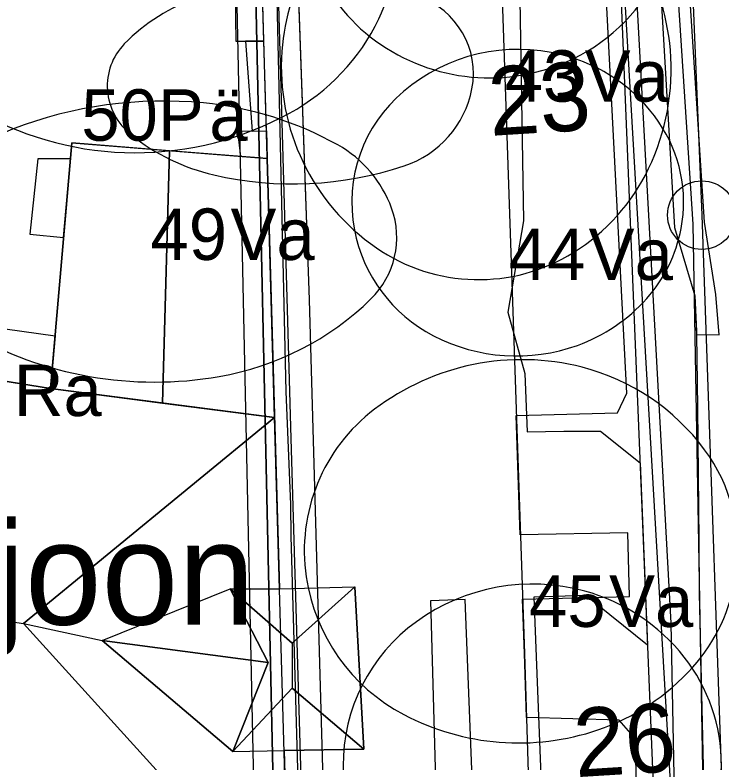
# Model space of a CAD drawing. Extents: x 738423 to 738903, y 6589762 to 6590172.
# Drawn here: x 738753.01 to 738773.59, y 6589853.54 to 6589875.33 of the extents above; entities that cross this region are included whole.
import ezdxf

# ---------------------------------------------------------------- set-up
doc = ezdxf.new("R2010")
doc.units = 0
for name, color, linetype in [('_1927_hoonestus', 7, 'Continuous'), ('_1927_katuse_kalded', 7, 'Continuous'), ('_1927_koordin_punktid_nr', 7, 'Continuous'), ('_1927_krundi_piir', 7, 'Continuous'), ('_a_olol_maapind', 7, 'Continuous'), ('_ajalooline_aadress', 7, 'Continuous'), ('a_dendro_II_Vkl_puu', 7, 'Continuous'), ('a_dendro_III_vk_puu', 7, 'Continuous'), ('a_dendro_puu_nr', 7, 'Continuous'), ('a_dendro_V_vk_puu', 7, 'Continuous'), ('a_kaitsealune_park', 7, 'Continuous'), ('a_LK_III_kodukakk', 7, 'Continuous'), ('Default', 7, 'Continuous'), ('plan_ala', 7, 'Continuous'), ('v_dp_jalak_liikumine', 7, 'Continuous'), ('v_olol_kitsendus_tehnov', 7, 'Continuous'), ('v_olol_kivimuur', 7, 'Continuous'), ('v_olol_transp_jjt_jalg', 7, 'Continuous'), ('v_olol_transp_tee', 7, 'Continuous')]:
    doc.layers.add(name, color=color, linetype=linetype)

# ---------------------------------------------------------------- blocks, each defined once
blk = doc.blocks.new('_U493')
at = {"layer": 'Default'}
for centre, radius, start, end in [((-0.002779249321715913, 0.004118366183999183), 0.010010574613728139, 80.44978915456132, 146.25517279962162), ((-0.0028357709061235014, 0.003782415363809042), 0.010351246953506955, 32.07722645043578, 80.44978915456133), ((-0.0017373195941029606, 0.003422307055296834), 0.011263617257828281, 146.2551727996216, 207.86384233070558), ((-0.003686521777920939, 0.0032492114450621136), 0.011355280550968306, 346.0222805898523, 32.077226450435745), ((-0.003267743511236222, 0.003144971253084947), 0.010923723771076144, 317.781064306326, 346.0222805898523), ((-0.0022155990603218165, 0.0031694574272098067), 0.010722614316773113, 207.8638423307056, 247.1920387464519), ((-0.002627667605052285, 0.0025642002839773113), 0.010059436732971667, 288.3253318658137, 317.78106430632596), ((-0.00255825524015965, 0.002354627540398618), 0.009838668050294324, 247.19203874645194, 288.3253318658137)]:
    blk.add_arc(centre, radius, start, end, dxfattribs=at)
blk = doc.blocks.new('_U494')
at = {"layer": 'Default'}
for centre, radius, start, end in [((-0.0012102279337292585, 0.0031557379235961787), 0.012828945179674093, 90.26069818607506, 149.67736093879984), ((-0.001211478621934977, 0.0034306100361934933), 0.012554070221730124, 36.73116784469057, 90.26069818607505), ((0.000498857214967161, 0.004706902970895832), 0.010420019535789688, 337.48443189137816, 36.73116784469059), ((-0.0032425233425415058, 0.004344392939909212), 0.010474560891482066, 149.67736093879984, 216.20034037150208), ((-0.0005155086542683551, 0.005127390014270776), 0.011518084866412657, 307.20500292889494, 337.48443189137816), ((-0.002245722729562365, 0.005073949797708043), 0.011709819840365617, 216.20034037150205, 248.7506077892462), ((-0.0015898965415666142, 0.006542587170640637), 0.013294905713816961, 279.06638207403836, 307.20500292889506), ((-0.0016145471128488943, 0.006697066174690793), 0.013451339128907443, 248.75060778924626, 279.06638207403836)]:
    blk.add_arc(centre, radius, start, end, dxfattribs=at)
blk = doc.blocks.new('_U495')
at = {"layer": 'Default'}
for centre, radius, start, end in [((0.001247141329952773, 0.003809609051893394), 0.008480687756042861, 44.522724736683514, 105.14224422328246), ((0.0013373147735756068, 0.003476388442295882), 0.008825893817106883, 105.14224422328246, 156.90409293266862), ((-0.00011059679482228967, 0.0024743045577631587), 0.01038502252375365, 350.25622703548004, 44.52272473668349), ((0.0028799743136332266, 0.0028185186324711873), 0.01050297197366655, 156.9040929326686, 204.0776996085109), ((0.0005376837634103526, 0.0023629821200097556), 0.009727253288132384, 308.7697621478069, 350.25622703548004), ((0.002304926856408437, 0.0025615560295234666), 0.009873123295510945, 204.0776996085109, 232.70014380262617), ((0.00146564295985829, 0.0012075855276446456), 0.008245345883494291, 263.520272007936, 308.7697621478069), ((0.0014993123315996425, 0.0015040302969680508), 0.008543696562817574, 232.70014380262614, 263.520272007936)]:
    blk.add_arc(centre, radius, start, end, dxfattribs=at)
blk = doc.blocks.new('_U496')
at = {"layer": 'Default'}
for centre, radius, start, end in [((0.001006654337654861, 0.005865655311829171), 0.010371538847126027, 41.52685359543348, 102.67231492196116), ((0.0011174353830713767, 0.005372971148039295), 0.010876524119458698, 102.67231492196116, 156.5695222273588), ((-0.0018463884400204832, 0.0033391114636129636), 0.014182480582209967, 349.9614071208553, 41.52685359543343), ((0.0043186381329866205, 0.003985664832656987), 0.014365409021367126, 156.56952222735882, 203.0187686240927), ((-0.0005003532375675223, 0.003100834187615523), 0.012815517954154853, 310.73435045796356, 349.96140712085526), ((0.003089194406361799, 0.0034633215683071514), 0.013029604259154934, 203.0187686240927, 232.53618152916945), ((0.0014401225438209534, 0.0013113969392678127), 0.01031847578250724, 232.5361815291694, 265.8052878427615), ((0.0014087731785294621, 0.0008839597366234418), 0.009889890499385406, 265.8052878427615, 310.7343504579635)]:
    blk.add_arc(centre, radius, start, end, dxfattribs=at)
blk = doc.blocks.new('_U497')
at = {"layer": 'Default'}
for centre, radius, start, end in [((-0.0002784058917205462, 0.0036950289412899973), 0.010329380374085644, 94.66436035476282, 151.30931070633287), ((-0.00027800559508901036, 0.0036901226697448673), 0.010334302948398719, 40.2654876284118, 94.66436035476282), ((-0.0011843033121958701, 0.0029224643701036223), 0.011522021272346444, 348.96331862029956, 40.265487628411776), ((0.0007686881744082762, 0.00312198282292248), 0.01152302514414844, 151.30931070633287, 204.69265836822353), ((-0.0007788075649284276, 0.0028433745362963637), 0.01110888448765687, 312.4366755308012, 348.96331862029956), ((0.0003699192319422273, 0.0029386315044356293), 0.011084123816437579, 204.69265836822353, 238.61349672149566), ((-0.00011649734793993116, 0.002118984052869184), 0.01012735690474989, 274.1151503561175, 312.43667553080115), ((-0.00011793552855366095, 0.0021389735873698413), 0.010147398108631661, 238.6134967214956, 274.1151503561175)]:
    blk.add_arc(centre, radius, start, end, dxfattribs=at)
blk = doc.blocks.new('_U500')
at = {"layer": 'Default'}
for centre, radius, start, end in [((-0.003181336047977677, 0.010726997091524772), 0.005594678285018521, 70.00824536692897, 154.4975713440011), ((-0.004341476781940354, 0.007538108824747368), 0.008988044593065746, 25.436486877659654, 70.00824536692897), ((0.011580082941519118, 0.0036853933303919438), 0.021949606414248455, 154.49757134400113, 194.18050981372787), ((-0.018263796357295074, 0.0009164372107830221), 0.024404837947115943, 358.8256663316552, 25.436486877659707), ((-0.0137456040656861, 0.0008238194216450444), 0.019885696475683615, 335.045242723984, 358.8256663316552), ((0.0065598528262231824, 0.0024168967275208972), 0.01677159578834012, 194.18050981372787, 228.62130685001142), ((-0.0020266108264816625, -0.004629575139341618), 0.006959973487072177, 294.2825804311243, 335.045242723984), ((-0.0012209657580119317, -0.006415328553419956), 0.005000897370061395, 228.6213068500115, 294.2825804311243)]:
    blk.add_arc(centre, radius, start, end, dxfattribs=at)
blk = doc.blocks.new('_U501')
at = {"layer": 'Default'}
for centre, radius, start, end in [((6.853040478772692e-05, 0.0017748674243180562), 0.0034801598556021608, 50.02426182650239, 98.69184032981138), ((0.00010234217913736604, 0.0015536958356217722), 0.003703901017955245, 98.69184032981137, 145.7521009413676), ((-0.0047346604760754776, -0.003954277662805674), 0.010956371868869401, 23.167488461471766, 50.0242618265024), ((0.007022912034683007, -0.003157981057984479), 0.012076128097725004, 145.7521009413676, 171.29949798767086), ((-0.01307393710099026, -0.007522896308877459), 0.020027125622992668, 345.8050064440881, 23.167488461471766), ((0.015367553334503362, -0.004434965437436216), 0.020517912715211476, 171.29949798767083, 202.7206439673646), ((0.0019149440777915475, -0.01006800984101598), 0.00593354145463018, 202.7206439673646, 263.18793889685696), ((0.0017704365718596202, -0.011277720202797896), 0.004715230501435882, 263.18793889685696, 345.8050064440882)]:
    blk.add_arc(centre, radius, start, end, dxfattribs=at)
blk = doc.blocks.new('_U502')
at = {"layer": 'Default'}
for centre, radius, start, end in [((0.0036572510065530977, 0.004633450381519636), 0.00959048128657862, 55.41358266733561, 119.34866517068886), ((0.004842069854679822, 0.0025263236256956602), 0.012007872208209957, 119.34866517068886, 155.37187783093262), ((-0.0003045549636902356, -0.0011124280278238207), 0.016569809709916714, 7.908336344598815, 55.413582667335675), ((0.010745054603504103, -0.00017977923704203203), 0.018501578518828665, 155.37187783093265, 184.22093899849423), ((-0.0007628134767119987, -0.0011760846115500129), 0.017032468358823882, 317.51230780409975, 7.908336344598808), ((0.010991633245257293, -0.00016158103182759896), 0.018748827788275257, 184.2209389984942, 213.03615061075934), ((0.005634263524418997, -0.0036455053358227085), 0.01235827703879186, 213.03615061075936, 248.72963133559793), ((0.004661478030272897, -0.006144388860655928), 0.009676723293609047, 248.72963133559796, 317.51230780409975)]:
    blk.add_arc(centre, radius, start, end, dxfattribs=at)

msp = doc.modelspace()

# ---------------------------------------------------------------- linework, layer by layer
at = {"layer": '_1927_hoonestus'}
for points in [[(738759.445913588, 6589874.562185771), (738760.2651028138, 6589874.562658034), (738759.9817993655, 6589884.477955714), (738750.4259107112, 6589885.542779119), (738750.3212133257, 6589884.603208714), (738759.3147045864, 6589883.851353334)], [(738754.6692785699, 6589871.594604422), (738760.36289178, 6589871.140155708), (738760.7214549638, 6589858.590853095), (738762.9217034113, 6589858.653719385), (738763.1765392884, 6589853.918763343), (738760.8559821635, 6589853.882554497), (738760.9939902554, 6589849.052428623), (738727.0653921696, 6589854.4155183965), (738729.4713935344, 6589879.48149063), (738730.9007906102, 6589879.344287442), (738730.7635874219, 6589877.914890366), (738731.4712535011, 6589877.903268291), (738731.3149034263, 6589876.439602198), (738734.6501282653, 6589876.083330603), (738734.035737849, 6589870.331734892), (738732.4870712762, 6589870.497164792), (738732.2152484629, 6589867.952504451), (738754.0513227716, 6589864.430896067)], [(738759.7303753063, 6589874.562349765), (738759.9252105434, 6589871.941606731), (738760.3398218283, 6589871.9475777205), (738760.265102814, 6589874.562658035)], [(738759.597844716, 6589871.2012196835), (738759.5105992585, 6589871.935635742), (738760.3398218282, 6589871.9475777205), (738760.36289178, 6589871.140155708)], [(738754.6296711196, 6589871.135451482), (738753.6793294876, 6589871.135451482), (738753.4529296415, 6589868.936854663), (738754.4312025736, 6589868.834686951)], [(738751.5721327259, 6589864.83072693), (738751.7504285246, 6589866.314167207), (738754.1842644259, 6589865.972034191), (738754.0513227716, 6589864.430896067)]]:
    msp.add_lwpolyline(points, close=True, dxfattribs=at)
at = {"layer": '_1927_katuse_kalded'}
for points in [[(738757.5160851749, 6589871.367380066), (738754.6692785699, 6589871.594604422), (738754.0513228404, 6589864.430896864), (738757.3149887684, 6589864.009796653)], [(738757.5160851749, 6589871.367380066), (738757.3149887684, 6589864.009796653), (738760.5786547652, 6589863.588697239), (738760.36289178, 6589871.140155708)], [(738753.2610349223, 6589857.584302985), (738760.578654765, 6589863.588697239), (738754.0513227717, 6589864.430896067), (738732.2152484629, 6589867.952504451), (738728.4114490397, 6589868.438878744), (738727.7392322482, 6589861.435654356)], [(738753.261203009, 6589857.584117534), (738755.5508360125, 6589857.086946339), (738759.2857264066, 6589858.5929717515), (738760.7214549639, 6589858.590853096), (738760.5786547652, 6589863.588697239)], [(738753.2610349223, 6589857.584302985), (738760.9939902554, 6589849.052428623), (738727.0653912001, 6589854.415518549), (738727.7392322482, 6589861.435654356)], [(738759.2857264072, 6589858.5929717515), (738760.3875600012, 6589856.448334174), (738755.5508360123, 6589857.086946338), (738755.5508360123, 6589857.086946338)], [(738762.9217034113, 6589858.653719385), (738761.0928823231, 6589857.008580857), (738759.2857264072, 6589858.592971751), (738760.7214549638, 6589858.590853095)], [(738761.0928823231, 6589857.008580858), (738761.0928823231, 6589855.692730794), (738759.3629081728, 6589853.853042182), (738760.3875600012, 6589856.448334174), (738759.2857264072, 6589858.592971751)], [(738762.9217034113, 6589858.653719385), (738761.0928823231, 6589857.008580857), (738761.0928823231, 6589855.692730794), (738763.1765392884, 6589853.918763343)], [(738753.2610349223, 6589857.584302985), (738755.5508360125, 6589857.086946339), (738759.3629081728, 6589853.853042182), (738760.8559821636, 6589853.882554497), (738760.9939902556, 6589849.052428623)], [(738755.5508360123, 6589857.086946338), (738760.3875600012, 6589856.448334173), (738759.3629081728, 6589853.853042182)], [(738759.3629081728, 6589853.853042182), (738760.8559821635, 6589853.882554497), (738763.1765392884, 6589853.918763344), (738761.0928823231, 6589855.692730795)]]:
    msp.add_lwpolyline(points, close=True, dxfattribs=at)
at = {"layer": '_1927_koordin_punktid_nr'}
msp.add_circle((738773.0279139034, 6589869.489296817), 0.9999999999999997, dxfattribs=at)
at = {"layer": '_1927_krundi_piir'}
for points in [[(738850.0095657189, 6589989.55232978), (738833.7612257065, 6589994.011774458), (738785.7861100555, 6589991.79782363), (738784.779371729, 6590001.213474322), (738769.6219465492, 6589952.2375112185), (738773.0279139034, 6589869.489296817), (738773.7385420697, 6589849.214289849)], [(738727.0653921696, 6589854.415518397), (738760.9939902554, 6589849.052428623), (738759.9817993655, 6589884.477955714), (738730.2687956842, 6589887.788909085)]]:
    msp.add_lwpolyline(points, dxfattribs=at)
at = {"layer": 'a_kaitsealune_park'}
for points in [[(738799.76, 6589792.27), (738785.86, 6589778.87), (738784.7, 6589778.87), (738782.88, 6589779.529999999), (738781.39, 6589772.739999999), (738771.13, 6589773.569999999), (738772.7799999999, 6589780.85), (738773.44, 6589784.33), (738773.94, 6589792.27), (738774.27, 6589803.029999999), (738773.7799999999, 6589812.8), (738772.7799999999, 6589869.2299999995), (738770.47, 6589904.4799999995), (738769.7999999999, 6589927.489999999), (738768.64, 6589952.319999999), (738783.87, 6590000.64), (738772.45, 6589999.4799999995), (738769.3099999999, 6590021.66), (738764.34, 6590055.09)], [(738799.7600000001, 6589792.2700000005), (738785.8600000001, 6589778.87), (738784.7000000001, 6589778.87), (738782.8800000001, 6589779.529999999), (738781.3900000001, 6589772.739999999), (738771.1300000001, 6589773.57), (738772.7800000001, 6589780.85), (738773.4400000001, 6589784.33), (738773.9400000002, 6589792.2700000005), (738774.2700000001, 6589803.029999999), (738773.7800000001, 6589812.8), (738772.7800000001, 6589869.2299999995), (738770.4700000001, 6589904.4799999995), (738769.8000000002, 6589927.489999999), (738768.6400000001, 6589952.32), (738783.8700000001, 6590000.64), (738772.4500000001, 6589999.4799999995), (738769.31, 6590021.66), (738764.3400000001, 6590055.090000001)]]:
    msp.add_lwpolyline(points, dxfattribs=at)
at = {"layer": 'a_LK_III_kodukakk'}
for points in [[(738774.7994326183, 6589988.285599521), (738764.1399073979, 6589986.277146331), (738769.1897073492, 6589903.198381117), (738776.335723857, 6589779.97210939), (738793.4555446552, 6589779.000724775), (738813.3159401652, 6589799.458179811), (738821.0361855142, 6589844.984582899), (738829.6606448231, 6589892.216196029), (738831.9963747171, 6589940.607262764), (738821.771276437, 6589948.753911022), (738824.9825951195, 6589976.648101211)], [(738824.9825951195, 6589976.648101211), (738774.7994326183, 6589988.285599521), (738764.1399073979, 6589986.277146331), (738765.2872134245, 6589967.401791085), (738769.1897073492, 6589903.198381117), (738776.335723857, 6589779.97210939), (738793.4555446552, 6589779.000724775), (738813.3159401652, 6589799.458179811), (738813.3159401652, 6589799.458179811), (738821.0361855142, 6589844.984582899), (738829.6606448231, 6589892.216196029), (738831.9963747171, 6589940.607262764), (738821.771276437, 6589948.753911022), (738823.7390795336, 6589965.8466630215)]]:
    msp.add_lwpolyline(points, close=True, dxfattribs=at)
at = {"layer": 'plan_ala'}
msp.add_lwpolyline([(738772.2221966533, 6589837.873120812), (738583.11, 6589865.669999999), (738583.11, 6589865.669999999), (738577.13, 6589865.85), (738565.7035831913, 6589866.139410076), (738565.4500000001, 6589885.77), (738564.4932191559, 6589941.052825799), (738581.9, 6589941.1499999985), (738615.11, 6589942.169999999), (738650.0499999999, 6589943.319999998), (738691.2690631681, 6589944.800325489), (738696.0901513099, 6589944.851371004), (738713.89, 6589945.129999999), (738703.51, 6589987.789999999), (738752.8799999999, 6590000.39), (738783.1408503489, 6590007.463828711), (738767.5688789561, 6589951.87996157)], close=True, dxfattribs=at)
at = {"layer": 'v_dp_jalak_liikumine'}
for points in [[(738772.8314907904, 6589822.05422032), (738772.1326963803, 6589857.588990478), (738770.9620988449, 6589879.067946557), (738769.8762536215, 6589900.994088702), (738769.0280300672, 6589927.1195196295), (738768.174597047, 6589945.0336976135), (738767.9949961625, 6589954.493808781), (738767.592362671, 6589970.544603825), (738766.4174611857, 6590002.737088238), (738765.5686251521, 6590014.935694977)], [(738753.7352778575, 6590011.485218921), (738754.5485713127, 6589968.543440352), (738755.4664630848, 6589938.81512126), (738757.0489483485, 6589902.976712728), (738757.749514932, 6589889.633197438), (738760.3964895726, 6589885.01045508), (738760.6563499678, 6589876.988192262), (738761.0572489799, 6589862.973393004), (738761.3980093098, 6589851.105365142), (738761.7912117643, 6589844.0801351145)]]:
    msp.add_lwpolyline(points, dxfattribs=at)
at = {"layer": 'v_olol_kitsendus_tehnov'}
for p, q in [((738769.644962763, 6589858.400362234), (738768.1292060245, 6589858.347468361)), ((738771.4435040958, 6589856.951181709), (738769.644962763, 6589858.400362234)), ((738766.1304018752, 6589858.277718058), (738765.1219028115, 6589858.242525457)), ((738765.1219028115, 6589858.242525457), (738765.6759919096, 6589838.835322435))]:
    msp.add_line(p, q, dxfattribs=at)
for points in [[(738767.3745934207, 6589881.674000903), (738767.6679919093, 6589879.3007331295), (738767.8313870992, 6589869.325507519), (738767.3763574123, 6589866.656381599), (738767.8716338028, 6589864.87470985), (738767.9387250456, 6589863.174523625)], [(738765.6759919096, 6589838.835322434), (738761.6574981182, 6589839.4259854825), (738761.0663960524, 6589860.129583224), (738761.0536354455, 6589861.049149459), (738760.9189495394, 6589864.350947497), (738760.6233662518, 6589877.039027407)], [(738767.9387250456, 6589863.174523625), (738769.0043696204, 6589863.19071795), (738770.0750587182, 6589863.19071795), (738771.2267054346, 6589862.262774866), (738771.4435040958, 6589856.95118171)], [(738768.880591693, 6589838.364290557), (738766.8696105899, 6589838.659876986), (738766.6778052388, 6589844.405748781), (738766.1304018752, 6589858.277718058)], [(738768.1292060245, 6589858.347468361), (738768.676489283, 6589844.4785427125), (738768.880591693, 6589838.364290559)]]:
    msp.add_lwpolyline(points, dxfattribs=at)
at = {"layer": 'v_olol_kivimuur'}
msp.add_lwpolyline([(738773.551447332, 6589967.920285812), (738768.7339999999, 6589952.588000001), (738769.0466151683, 6589943.94935574), (738769.4269999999, 6589933.438000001), (738770.2589999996, 6589909.592000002), (738770.9589999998, 6589890.911999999), (738772.232, 6589869.133), (738772.826, 6589867.133999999), (738772.8770000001, 6589866.007000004), (738773.531, 6589865.9969999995), (738773.435, 6589867.171000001), (738773.1038480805, 6589869.28868809), (738772.3156105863, 6589881.477120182), (738771.618274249, 6589894.965283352), (738770.8885638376, 6589915.587099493), (738770.3453820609, 6589932.01901282), (738769.6675069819, 6589952.525563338), (738775.8349999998, 6589971.891)], dxfattribs=at)
msp.add_lwpolyline([(738760.0570706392, 6589848.878675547), (738760.6230000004, 6589848.891), (738759.843, 6589884.707999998), (738759.3080000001, 6589883.751999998), (738760.0570706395, 6589848.878675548)], close=True, dxfattribs=at)
at = {"layer": 'v_olol_transp_jjt_jalg'}
for points in [[(738753.3980000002, 6589984.476), (738754.3250000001, 6589953.163999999), (738755.04, 6589926.637), (738755.4860000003, 6589911.220000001), (738756.5250000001, 6589889.759999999), (738757.82206961, 6589886.935068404), (738757.3703897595, 6589885.530282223), (738754.0880000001, 6589882.902000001), (738752.2950952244, 6589882.167957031), (738745.265557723, 6589881.245987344), (738738.6560000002, 6589881.396000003), (738727.6409999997, 6589881.646000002), (738723.8518062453, 6589881.6181833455), (738723.8688999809, 6589879.598070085), (738727.889, 6589879.6620000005), (738739.6499999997, 6589879.9520000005), (738745.5079999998, 6589880.3), (738753.9679999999, 6589881.731000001), (738758.1444489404, 6589884.291527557), (738759.843, 6589884.707999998), (738760.6230000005, 6589848.891)], [(738762.2380000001, 6589844.465999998), (738761.5959999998, 6589867.022999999), (738760.9699535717, 6589884.81262032), (738760.8657554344, 6589887.773495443), (738759.372430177, 6589888.584165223), (738758.4950000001, 6589889.556), (738757.792, 6589911.368000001), (738757.1080000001, 6589928.520999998), (738756.3560000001, 6589953.211999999), (738755.3990000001, 6589984.343999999)], [(738771.2460000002, 6589845.951999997), (738771.1, 6589854.219999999), (738770.623, 6589854.761999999), (738767.9149902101, 6589854.837815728), (738767.8570000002, 6589856.707999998), (738767.80323949, 6589858.286510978), (738770.9189999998, 6589858.366000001), (738770.8716205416, 6589860.223150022), (738767.7391716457, 6589860.167664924), (738767.6206702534, 6589863.647091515), (738770.567, 6589863.728), (738770.845, 6589864.293999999), (738769.465, 6589890.928999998), (738767.908, 6589933.227999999), (738767.211, 6589952.575000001), (738766.3339999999, 6589982.853999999)], [(738773.551447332, 6589967.920285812), (738768.7339999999, 6589952.588000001), (738769.0466151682, 6589943.949355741), (738769.4269999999, 6589933.438000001), (738770.2589999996, 6589909.592000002), (738770.9589999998, 6589890.911999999), (738772.232, 6589869.133), (738772.826, 6589867.133999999), (738772.8770000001, 6589866.106999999), (738772.8769999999, 6589866.006999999), (738772.897, 6589863.881), (738772.9371575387, 6589859.993606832), (738772.953, 6589858.46), (738773.0395481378, 6589854.68389289), (738773.245, 6589845.720000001)]]:
    msp.add_lwpolyline(points, dxfattribs=at)
at = {"layer": 'v_olol_transp_tee'}
msp.add_lwpolyline([(738757.0262586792, 6590012.291021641), (738763.0496415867, 6590013.8166144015), (738763.91, 6589983.1489999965), (738764.929, 6589952.457999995), (738765.4810000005, 6589931.862999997), (738766.1660000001, 6589909.860999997), (738766.7020000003, 6589890.6209999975), (738767.8570000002, 6589856.707999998), (738768.121, 6589848.193999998), (738768.8037483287, 6589822.631606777), (738762.8293167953, 6589823.607741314), (738762.2380000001, 6589844.465999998), (738761.5959999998, 6589867.022999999), (738760.8119999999, 6589889.301), (738760.2139999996, 6589908.838999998), (738759.598, 6589929.524999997), (738758.8590000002, 6589952.364999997), (738757.8280000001, 6589984.569999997), (738757.361, 6590000.716999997)], close=True, dxfattribs=at)

# ---------------------------------------------------------------- block references
at = {"layer": 'a_dendro_II_Vkl_puu', "xscale": 500.0000000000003, "yscale": 500.0000000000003, "rotation": 85.69234851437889}
msp.add_blockref('_U502', (738756.0163105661, 6589875.209442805), dxfattribs=at)
at = {"layer": 'a_dendro_III_vk_puu', "xscale": 500.0000000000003, "yscale": 500.0000000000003, "rotation": 85.69234851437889}
for name, p in [('_U493', (738768.6093105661, 6589879.861442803)), ('_U494', (738768.8083105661, 6589874.299442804)), ('_U501', (738758.3273105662, 6589873.1634428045)), ('_U500', (738758.4873105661, 6589869.684442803)), ('_U496', (738769.517310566, 6589858.978442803)), ('_U497', (738769.594310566, 6589853.450442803))]:
    msp.add_blockref(name, p, dxfattribs=at)
at = {"layer": 'a_dendro_V_vk_puu', "xscale": 500.0000000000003, "yscale": 500.0000000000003, "rotation": 85.69234851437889}
msp.add_blockref('_U495', (738768.9223105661, 6589869.092442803), dxfattribs=at)

# ---------------------------------------------------------------- texts
at = {"layer": '_1927_koordin_punktid_nr'}
for s, p in [('23', (738766.8663827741, 6589871.79937715)), ('26', (738769.353279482, 6589853.097809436))]:
    msp.add_text(s, height=1.9999999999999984, rotation=3.560863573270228, dxfattribs=at).set_placement(p)
at = {"layer": '_a_olol_maapind'}
msp.add_text('räästajoon ', height=3, dxfattribs=at).set_placement((738741.2679981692, 6589857.548758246))
at = {"layer": '_ajalooline_aadress'}
msp.add_text('28, Lavretsovi maja', height=1.2, rotation=351.6029994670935, dxfattribs=at).set_placement((738739.5649350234, 6589854.2859480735))
at = {"layer": 'a_dendro_puu_nr'}
for s, p in [('43', (738767.2852681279, 6589872.797022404)), ('Va', (738769.6161003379, 6589872.797022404)), ('50P', (738754.9472183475, 6589871.6579528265)), ('ä', (738758.6757313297, 6589871.6579528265)), ('49', (738756.9642681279, 6589868.182022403)), ('Va', (738759.295100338, 6589868.182022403)), ('44', (738767.3992681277, 6589867.596161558)), ('Va', (738769.7301003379, 6589867.596161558)), ('Ra', (738752.9807939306, 6589863.630473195)), ('45', (738767.9942681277, 6589857.482161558)), ('Va', (738770.3251003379, 6589857.482161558))]:
    msp.add_text(s, height=1.5, dxfattribs=at).set_placement(p)

doc.saveas('drawing.dxf')
